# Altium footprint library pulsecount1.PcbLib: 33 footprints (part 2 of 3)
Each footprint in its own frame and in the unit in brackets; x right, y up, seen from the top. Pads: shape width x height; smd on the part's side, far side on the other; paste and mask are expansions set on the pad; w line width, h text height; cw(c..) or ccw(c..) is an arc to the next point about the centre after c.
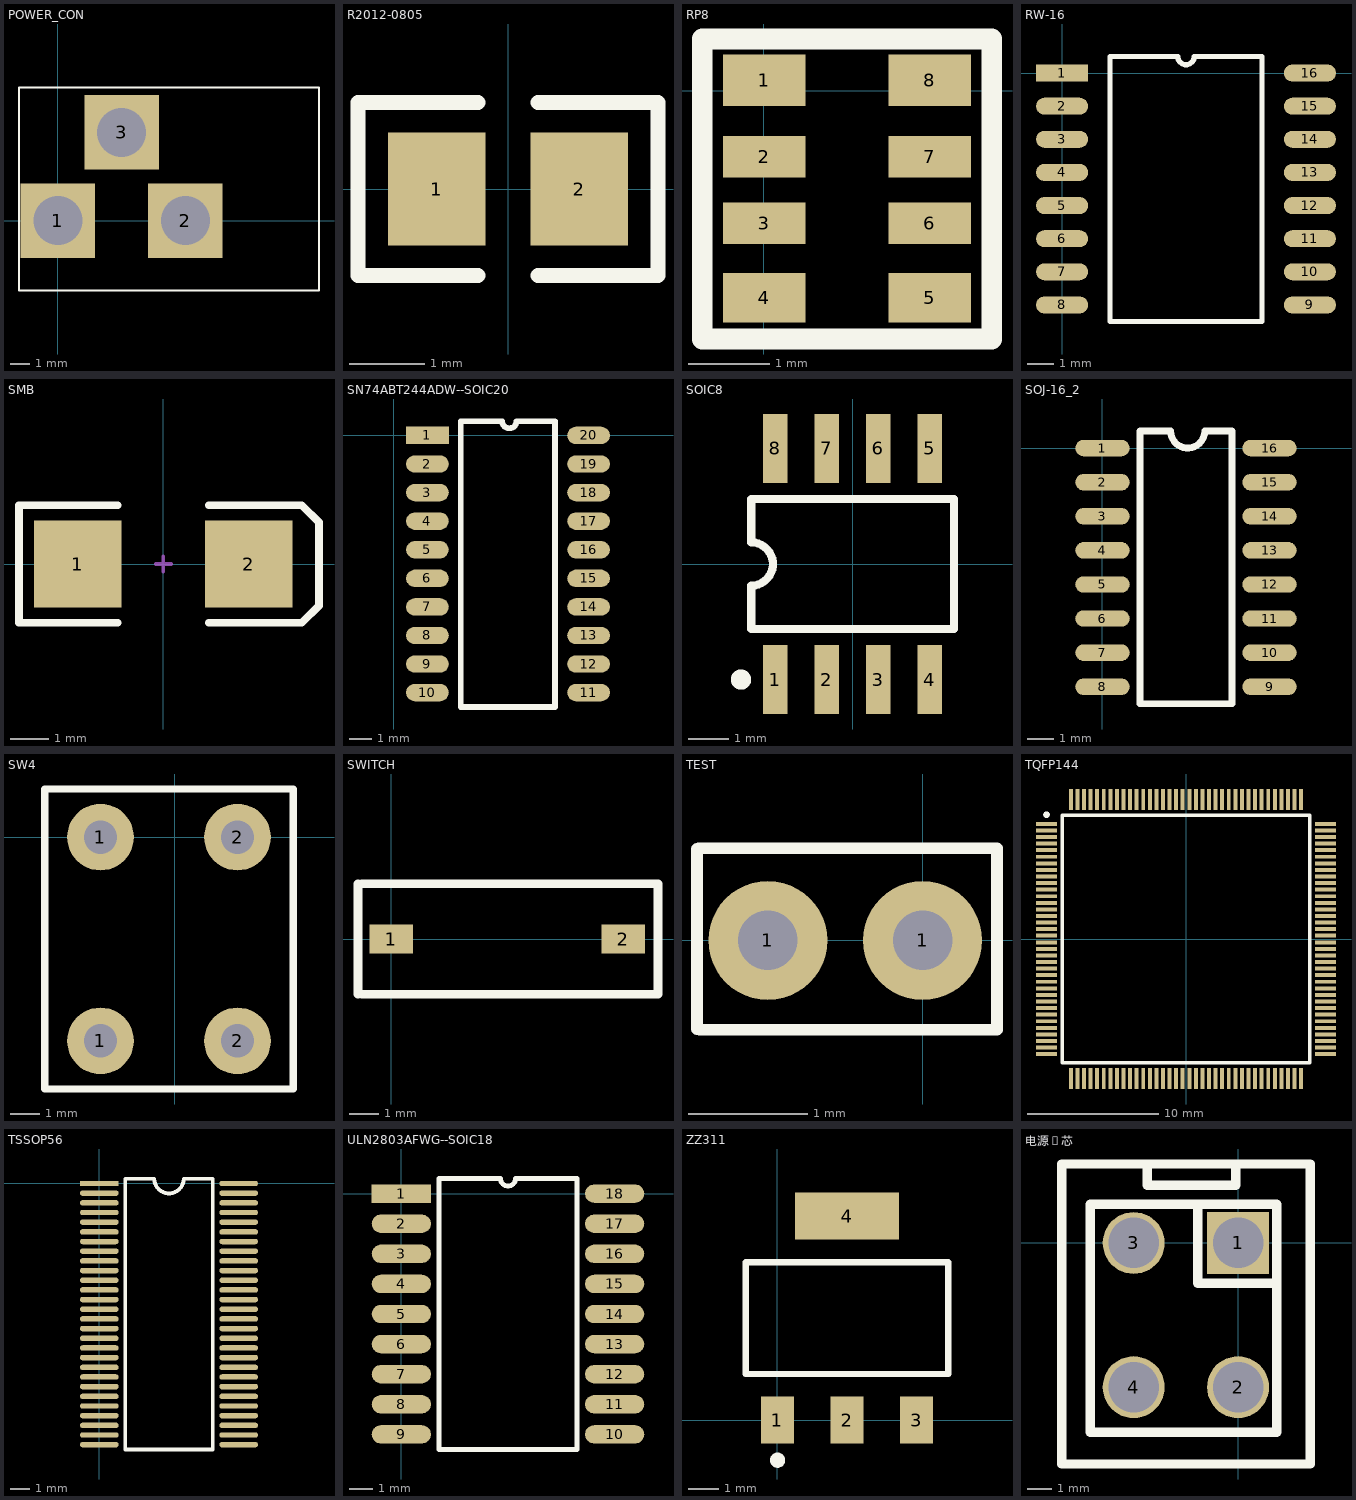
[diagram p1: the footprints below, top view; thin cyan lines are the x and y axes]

## POWER_CON [mm]
pads (3):
  rect 3.8x3.8 hole 2.5: 1(0,0) 2(6.5,0) 3(3.25,4.5)
Top Overlay:
  lines w0.102: -1.981,-3.556 13.31,-3.556 13.31,6.782 -1.981,6.782 -1.981,-3.556

## R2012-0805 [mm]
pads (2):
  rect 1.3x1.5 smd: 1(-0.95,0) 2(0.95,0)
Top Overlay:
  lines w0.2: -0.4,-1.15 -2,-1.15 -2,1.15 -0.4,1.15 ; 0.4,-1.15 2,-1.15 2,1.15 0.4,1.15

## RP8 [mil]
pads (8):
  rect 40x25 smd: 1(0.29,5) 8(80.29,5)
  rect 40x20 smd: 2(0.29,-32) 3(0.29,-64) 6(80.29,-64) 7(80.29,-32)
  rect 40x24 smd: 4(0.29,-100) 5(80.29,-100)
Top Overlay:
  lines w10: -29.71,-120 110.29,-120 110.29,25 -29.71,25 -29.71,-120

## RW-16 [mm]
pads (16):
  rect 2x0.65 smd: 1(0,0)
  oval 2x0.65 smd: 2(0,-1.27) 3(0,-2.54) 4(0,-3.81) 5(0,-5.08) 6(0,-6.35) 7(0,-7.62) 8(0,-8.89) 9(9.5,-8.89) 10(9.5,-7.62) 11(9.5,-6.35) 12(9.5,-5.08) 13(9.5,-3.81) 14(9.5,-2.54) 15(9.5,-1.27) 16(9.5,0)
Top Overlay:
  lines w0.2: 1.835,-9.525 7.665,-9.525 7.665,0.635 5.067,0.635 cw(c4.75,0.635) 4.432,0.635 1.835,0.635 1.835,-9.525

## SMB [mm]
pads (2):
  rect 2.3x2.3 smd: 1(-2.25,0) 2(2.25,0)
Top Overlay:
  lines w0.2: -1.2,-1.55 -3.8,-1.55 -3.8,1.55 -1.2,1.55 ; 1.2,-1.55 3.65,-1.55 4.1,-1.1 4.1,1.1 3.65,1.55 1.2,1.55
Mechanical 1:
  lines w0.1: -0.2,0 0.2,0 ; 0,-0.2 0,0.2

## SN74ABT244ADW--SOIC20 [mm]
pads (20):
  rect 1.9x0.773 smd: 1(1.5,0)
  oval 1.9x0.773 smd: 2(1.5,-1.27) 3(1.5,-2.54) 4(1.5,-3.81) 5(1.5,-5.08) 6(1.5,-6.35) 7(1.5,-7.62) 8(1.5,-8.89) 9(1.5,-10.16) 10(1.5,-11.43) 11(8.66,-11.43) 12(8.66,-10.16) 13(8.66,-8.89) 14(8.66,-7.62) 15(8.66,-6.35) 16(8.66,-5.08) 17(8.66,-3.81) 18(8.66,-2.54) 19(8.66,-1.27) 20(8.66,0)
Top Overlay:
  lines w0.254: 2.981,-12.065 7.172,-12.065 7.172,0.635 5.457,0.635 cw(c5.14,0.635) 4.822,0.635 2.981,0.635 2.981,-12.065

## SOIC8 [mm]
pads (8):
  rect 0.6x1.7 smd: 1(-1.905,-2.85) 2(-0.635,-2.85) 3(0.635,-2.85) 4(1.905,-2.85) 5(1.905,2.85) 6(0.635,2.85) 7(-0.635,2.85) 8(-1.905,2.85)
Top Overlay:
  circle w0.25: c-2.755,-2.85 r0.125
  lines w0.2: -2.5,-0.533 -2.5,-1.6 2.5,-1.6 2.5,1.6 -2.5,1.6 -2.5,0.533 ; -2.5,-0.533 ccw(c-2.5,0) -2.5,0.533

## SOJ-16_2 [mil]
pads (16):
  oval 80x24 smd: 1(0,0) 2(0,-50) 3(0,-100) 4(0,-150) 5(0,-200) 6(0,-250) 7(0,-300) 8(0,-350) 9(245,-350) 10(245,-300) 11(245,-250) 12(245,-200) 13(245,-150) 14(245,-100) 15(245,-50) 16(245,0)
Top Overlay:
  lines w10: 55,-375 55,25 100,25 ccw(c125,25) 150,25 190,25 190,-375 55,-375

## SW4 [mil]
pads (4):
  round 90 hole 45: 1(-100,-275) 1(-100,0) 2(85,-275) 2(85,0)
Top Overlay:
  lines w10: -175,-340 -175,65 160,65 160,-340 -175,-340

## SWITCH [mm]
pads (2):
  rect 1.5x1 smd: 1(0,0) 2(8.001,0)
Top Overlay:
  lines w0.305: -1.143,-1.905 -1.143,1.905 ; -1.016,-1.905 9.191,-1.905 9.191,1.905 -1.016,1.905

## TEST [mm]
pads (2):
  round 1 hole 0.5: 1(-1.3,0) 1(0,0)
Top Overlay:
  lines w0.1: -1.895,-0.745 -1.895,0.77 ; -1.88,0.775 0.625,0.775 0.625,-0.74 ; -1.875,-0.75 0.625,-0.75

## TQFP144 [mm]
pads (144):
  rect 1.6x0.3 smd: 1(-10.6,8.75) 2(-10.6,8.25) 3(-10.6,7.75) 4(-10.6,7.25) 5(-10.6,6.75) 6(-10.6,6.25) 7(-10.6,5.75) 8(-10.6,5.25) 9(-10.6,4.75) 10(-10.6,4.25) 11(-10.6,3.75) 12(-10.6,3.25) 13(-10.6,2.75) 14(-10.6,2.25) 15(-10.6,1.75) 16(-10.6,1.25) 17(-10.6,0.75) 18(-10.6,0.25) 19(-10.6,-0.25) 20(-10.6,-0.75) 21(-10.6,-1.25) 22(-10.6,-1.75) 23(-10.6,-2.25) 24(-10.6,-2.75) 25(-10.6,-3.25) 26(-10.6,-3.75) 27(-10.6,-4.25) 28(-10.6,-4.75) 29(-10.6,-5.25) 30(-10.6,-5.75) 31(-10.6,-6.25) 32(-10.6,-6.75) 33(-10.6,-7.25) 34(-10.6,-7.75) 35(-10.6,-8.25) 36(-10.6,-8.75) 73(10.6,-8.75) 74(10.6,-8.25) 75(10.6,-7.75) 76(10.6,-7.25) 77(10.6,-6.75) 78(10.6,-6.25) 79(10.6,-5.75) 80(10.6,-5.25) 81(10.6,-4.75) 82(10.6,-4.25) 83(10.6,-3.75) 84(10.6,-3.25) 85(10.6,-2.75) 86(10.6,-2.25) 87(10.6,-1.75) 88(10.6,-1.25) 89(10.6,-0.75) 90(10.6,-0.25) 91(10.6,0.25) 92(10.6,0.75) 93(10.6,1.25) 94(10.6,1.75) 95(10.6,2.25) 96(10.6,2.75) 97(10.6,3.25) 98(10.6,3.75) 99(10.6,4.25) 100(10.6,4.75) 101(10.6,5.25) 102(10.6,5.75) 103(10.6,6.25) 104(10.6,6.75) 105(10.6,7.25) 106(10.6,7.75) 107(10.6,8.25) 108(10.6,8.75)
  rect 0.3x1.6 smd: 37(-8.75,-10.6) 38(-8.25,-10.6) 39(-7.75,-10.6) 40(-7.25,-10.6) 41(-6.75,-10.6) 42(-6.25,-10.6) 43(-5.75,-10.6) 44(-5.25,-10.6) 45(-4.75,-10.6) 46(-4.25,-10.6) 47(-3.75,-10.6) 48(-3.25,-10.6) 49(-2.75,-10.6) 50(-2.25,-10.6) 51(-1.75,-10.6) 52(-1.25,-10.6) 53(-0.75,-10.6) 54(-0.25,-10.6) 55(0.25,-10.6) 56(0.75,-10.6) 57(1.25,-10.6) 58(1.75,-10.6) 59(2.25,-10.6) 60(2.75,-10.6) 61(3.25,-10.6) 62(3.75,-10.6) 63(4.25,-10.6) 64(4.75,-10.6) 65(5.25,-10.6) 66(5.75,-10.6) 67(6.25,-10.6) 68(6.75,-10.6) 69(7.25,-10.6) 70(7.75,-10.6) 71(8.25,-10.6) 72(8.75,-10.6) 109(8.75,10.6) 110(8.25,10.6) 111(7.75,10.6) 112(7.25,10.6) 113(6.75,10.6) 114(6.25,10.6) 115(5.75,10.6) 116(5.25,10.6) 117(4.75,10.6) 118(4.25,10.6) 119(3.75,10.6) 120(3.25,10.6) 121(2.75,10.6) 122(2.25,10.6) 123(1.75,10.6) 124(1.25,10.6) 125(0.75,10.6) 126(0.25,10.6) 127(-0.25,10.6) 128(-0.75,10.6) 129(-1.25,10.6) 130(-1.75,10.6) 131(-2.25,10.6) 132(-2.75,10.6) 133(-3.25,10.6) 134(-3.75,10.6) 135(-4.25,10.6) 136(-4.75,10.6) 137(-5.25,10.6) 138(-5.75,10.6) 139(-6.25,10.6) 140(-6.75,10.6) 141(-7.25,10.6) 142(-7.75,10.6) 143(-8.25,10.6) 144(-8.75,10.6)
Top Overlay:
  circle w0.25: c-10.6,9.45 r0.125
  lines w0.254: -9.4,-9.4 9.4,-9.4 9.4,9.4 -9.4,9.4 -9.4,-9.4

## TSSOP56 [mm]
pads (56):
  rect 2x0.28 smd: 1(-0.003,-0.01)
  oval 2x0.28 smd: 2(-0.003,-0.51) 3(-0.003,-1.01) 4(-0.003,-1.51) 5(-0.003,-2.01) 6(-0.003,-2.51) 7(-0.003,-3.01) 8(-0.003,-3.51) 9(-0.003,-4.01) 10(-0.003,-4.51) 11(-0.003,-5.01) 12(-0.003,-5.51) 13(-0.003,-6.01) 14(-0.003,-6.51) 15(-0.003,-7.01) 16(-0.003,-7.51) 17(-0.003,-8.01) 18(-0.003,-8.51) 19(-0.003,-9.01) 20(-0.003,-9.51) 21(-0.003,-10.01) 22(-0.003,-10.51) 23(-0.003,-11.01) 24(-0.003,-11.51) 25(-0.003,-12.01) 26(-0.003,-12.51) 27(-0.003,-13.01) 28(-0.003,-13.51) 29(7.197,-13.51) 30(7.197,-13.01) 31(7.197,-12.51) 32(7.197,-12.01) 33(7.197,-11.51) 34(7.197,-11.01) 35(7.197,-10.51) 36(7.197,-10.01) 37(7.197,-9.51) 38(7.197,-9.01) 39(7.197,-8.51) 40(7.197,-8.01) 41(7.197,-7.51) 42(7.197,-7.01) 43(7.197,-6.51) 44(7.197,-6.01) 45(7.197,-5.51) 46(7.197,-5.01) 47(7.197,-4.51) 48(7.197,-4.01) 49(7.197,-3.51) 50(7.197,-3.01) 51(7.197,-2.51) 52(7.197,-2.01) 53(7.197,-1.51) 54(7.197,-1.01) 55(7.197,-0.51) 56(7.197,-0.01)
Top Overlay:
  lines w0.2: 1.332,-13.76 5.862,-13.76 5.862,0.24 4.357,0.24 cw(c3.597,0.24) 2.838,0.24 1.332,0.24 1.332,-13.76

## ULN2803AFWG--SOIC18 [mm]
pads (18):
  rect 2.5x0.773 smd: 1(0,0)
  oval 2.5x0.773 smd: 2(0,-1.27) 3(0,-2.54) 4(0,-3.81) 5(0,-5.08) 6(0,-6.35) 7(0,-7.62) 8(0,-8.89) 9(0,-10.16) 10(9,-10.16) 11(9,-8.89) 12(9,-7.62) 13(9,-6.35) 14(9,-5.08) 15(9,-3.81) 16(9,-2.54) 17(9,-1.27) 18(9,0)
Top Overlay:
  lines w0.2: 1.585,-10.795 7.415,-10.795 7.415,0.635 4.817,0.635 cw(c4.5,0.635) 4.182,0.635 1.585,0.635 1.585,-10.795

## ZZ311 [mm]
pads (4):
  rect 1.1x1.55 smd: 1(0,0) 2(2.3,0) 3(4.6,0)
  rect 3.45x1.55 smd: 4(2.3,6.75)
Top Overlay:
  circle w0.25: c0,-1.325 r0.125
  lines w0.2: -1.05,1.525 -1.05,5.225 5.65,5.225 5.65,1.525 -1.05,1.525

## 电源4芯 [mil]
pads (4):
  rect 98x98 hole 80: 1(0,0)
  round 98 hole 80: 2(0,-228.35) 3(-165.35,0) 4(-165.35,-228.35)
Bottom Layer:
  lines w10: -165.35,-228.35 -159.65,-228.35
Top Overlay:
  lines w15: -144,122 -144,91 -4,91 -4,117 ; -64,55 -64,-64 53.94,-64 ; -279,-350 -279,125 113.94,125 113.94,-350 -279,-350 ; -234,-300 -234,61 61,61 61,-300 -234,-300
